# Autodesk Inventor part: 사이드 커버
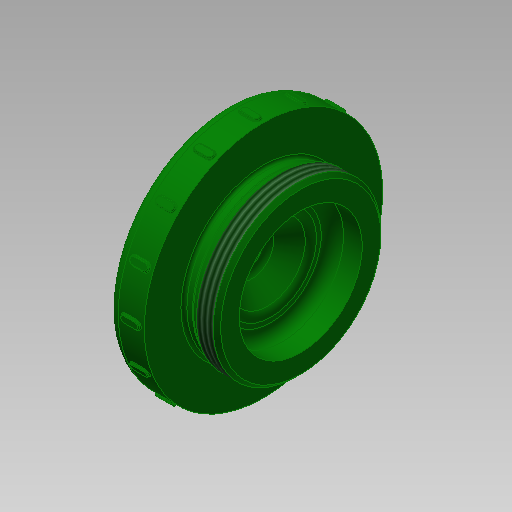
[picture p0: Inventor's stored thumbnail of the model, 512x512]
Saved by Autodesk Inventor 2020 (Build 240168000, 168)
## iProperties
Created: 2016-08
Part Number: 사이드 커버
Material: 스테인리스강
Document SubType Name: Modeling
Designer: mduedu
Density: 8.08 g/cm^3
Appearance: 진녹색
Author: mduedu
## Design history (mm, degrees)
sketch "스케치1"
  geometry: L1 (3, 0)-(10, 0); L2 (4, 24)-(4, 32); L3 (4, 32)-(14, 32); L4 (14, 32)-(14, 22.5); L5 (14, 22.5)-(24, 22.5); L6 (24, 22.5)-(24, 16.5); L7 (16, 11)-(10, 5); L8 (10, 5)-(10, 0); L9 (4, 24)-(0, 21.199); L10 (0, 21.199)-(0, 17.059); L11 (24, 16.5)-(16, 16.5); L12 (16, 16.5)-(16, 11); A1 r 50 centre (-47, 0) between (3, 0) and (0, 17.059); 1 further point
  constraints: 25 end point, 4 parallel, 4 perpendicular, 2 point on circle, 2 point on line, 1 centre point, 1 horizontal, 1 horizontal alignment, 1 vertical
  dimensions: "d2" = 64 diameter of L3 L1; "d3" = 45 diameter of L5 L1; "d5" = 6 distance of L5.end L6.end; "d35" = 48 diameter of L2.start L1; "d36" = 10 distance of L2.end L3.end; "d37" = 24 distance between parallel lines of L6 L10; "d39" = 125 deg angle of L10 L9; "d42" = 10 distance between parallel lines of L6 L4; "d44" = 3 distance of L1.start point (0, 0); "d45" = 50 radius of A1; "d47" = 135 deg angle of L7 L12; "d49" = 22 diameter of L7.start L1; "d50" = 8 distance between parallel lines of L6 L12; "d51" = 6 distance between parallel lines of L12 L8
revolve "회전1" sketch "스케치1" stored, may be unused: angle "d6" = 90 deg
fillet "모깎기1" dims "d7" = 3
sketch "스케치2"
  geometry: L1 (14, -32)-(14, 32) reference; L2 (14, 22.5)-(24, 22.5) reference; L3 (0, 0)-(14, 0); L4 (14, 22.5)-(18.492, 22.5); L5 (18.492, 22.5)-(16.5, 21.35); L6 (16.5, 21.35)-(14, 21.35); L7 (14, 21.35)-(14, 22.5)
  constraints: 10 end point, 1 horizontal, 1 midpoint, 1 parallel, 1 vertical
  dimensions: "d9" = 42.7 diameter of L6 L3; "d31" = 30 deg angle of L2 L5; "d32" = 2.5 distance from line of L1 L5.end
revolve "회전2" sketch "스케치2" stored, may be unused: angle "d10" = 90 deg
fillet "모깎기2" dims "d11" = 3, "d33" = 0.8
feature "스레드1" dims "d12" = 10, "d13" = 0
chamfer "모따기1" distance "d14" = 1; stored, may be unused: second distance "d15" = 2, angle "d16" = 45 deg
node "작업 평면1"
sketch "스케치3"
  geometry: L1 (-8, -1)-(-13, -1); L2 (-13, -1)-(-13, 1); L3 (-13, 1)-(-8, 1); L4 (-8, 1)-(-8, -1); 2 further points
  constraints: 8 end point, 2 parallel, 1 horizontal, 1 horizontal alignment, 1 midpoint, 1 perpendicular
  dimensions: "d18" = 2 distance of L3.end L1.start; "d20" = 5 distance of L1.start L1.end; "d41" = 8 distance from line of point (0, 0) L4
extrude "돌출1" join sketch "스케치3" stored distance "d22" = 10; taper "d23" = 0 deg
fillet "모깎기3" dims "d24" = 1
fillet "모깎기4" dims "d25" = 0.2
node "솔리드1"
pattern_circular "원형 패턴1" dims angle "d27" = 360 deg
other parameters: "d17" = 32.5
